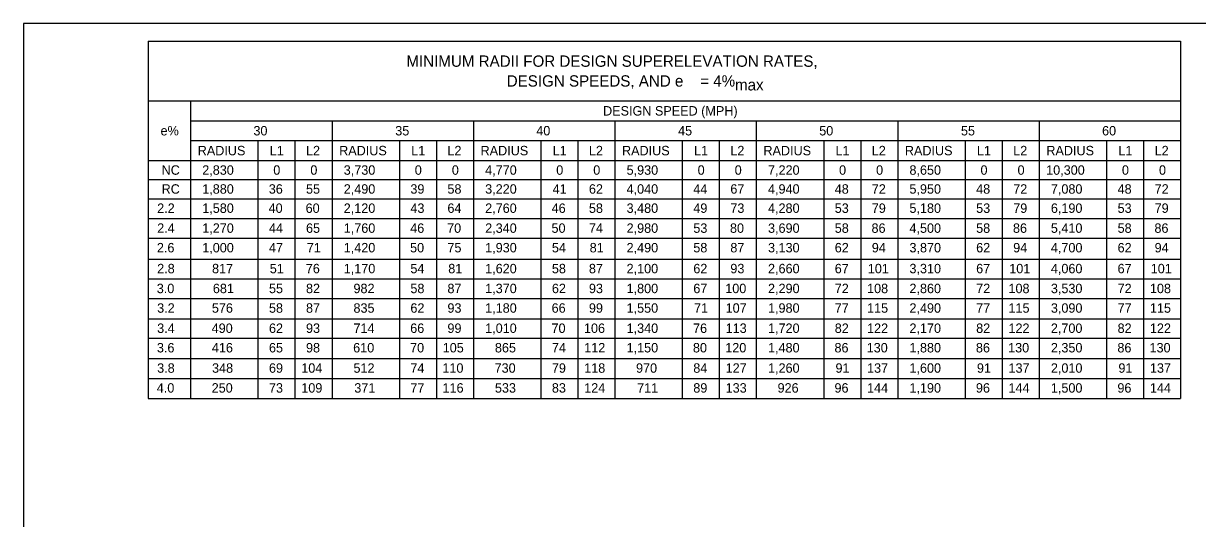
# Model space of a CAD drawing. Extents: x -404.8 to -373.6, y -458.1 to -437.7.
# Drawn here: x -404.83 to -386.16, y -445.54 to -437.68 of the extents above; entities that cross this region are included whole.
import ezdxf

# ---------------------------------------------------------------- set-up
doc = ezdxf.new("R2010")
doc.units = 0
for name, color, linetype in [('Bridge-Named Boundary', 7, 'Continuous'), ('Common-Notes', 7, 'Continuous'), ('Level 4', 7, 'Continuous')]:
    doc.layers.add(name, color=color, linetype=linetype)

msp = doc.modelspace()

# ---------------------------------------------------------------- linework, layer by layer
at = {"layer": 'Bridge-Named Boundary'}
msp.add_lwpolyline([(-404.826, -458.051), (-373.576, -458.051), (-373.576, -437.676), (-404.826, -437.676)], close=True, dxfattribs=at)
at = {"layer": 'Level 4'}
for p, q in [((-402.845, -437.957), (-386.425, -437.957)), ((-402.845, -437.957), (-402.845, -443.634)), ((-386.425, -437.957), (-386.425, -443.634)), ((-402.845, -438.906), (-386.425, -438.906)), ((-402.169, -438.906), (-402.169, -443.634)), ((-402.169, -439.222), (-386.425, -439.222)), ((-399.919, -439.222), (-399.919, -443.634)), ((-397.67, -439.222), (-397.67, -443.634)), ((-395.421, -439.222), (-395.421, -443.634)), ((-393.172, -439.222), (-393.172, -443.634)), ((-390.923, -439.222), (-390.923, -443.634)), ((-388.674, -439.222), (-388.674, -443.634)), ((-402.169, -439.538), (-386.425, -439.538)), ((-401.098, -439.538), (-401.098, -443.634)), ((-400.509, -439.538), (-400.509, -443.634)), ((-398.848, -439.538), (-398.848, -443.634)), ((-398.259, -439.538), (-398.259, -443.634)), ((-396.599, -439.538), (-396.599, -443.634)), ((-396.01, -439.538), (-396.01, -443.634)), ((-394.35, -439.538), (-394.35, -443.634)), ((-393.761, -439.538), (-393.761, -443.634)), ((-392.101, -439.538), (-392.101, -443.634)), ((-391.512, -439.538), (-391.512, -443.634)), ((-389.852, -439.538), (-389.852, -443.634)), ((-389.263, -439.538), (-389.263, -443.634)), ((-387.603, -439.538), (-387.603, -443.634)), ((-387.014, -439.538), (-387.014, -443.634)), ((-402.845, -439.855), (-386.425, -439.855)), ((-402.845, -440.155), (-386.425, -440.155)), ((-402.845, -440.461), (-386.425, -440.461)), ((-402.845, -440.777), (-386.425, -440.777)), ((-402.845, -441.088), (-386.425, -441.088)), ((-402.845, -441.42), (-386.425, -441.42)), ((-402.845, -441.736), (-386.425, -441.736)), ((-402.845, -442.047), (-386.425, -442.047)), ((-402.845, -442.369), (-386.425, -442.369)), ((-402.845, -442.679), (-386.425, -442.679)), ((-402.845, -443.001), (-386.425, -443.001)), ((-402.845, -443.317), (-386.425, -443.317)), ((-402.845, -443.634), (-386.425, -443.634))]:
    msp.add_line(p, q, dxfattribs=at)

# ---------------------------------------------------------------- texts
at = {"layer": 'Common-Notes'}
for s, height, p in [('MINIMUM RADII FOR DESIGN SUPERELEVATION RATES,', 0.18, (-398.737, -438.364)), ('DESIGN SPEEDS, AND e    = 4%', 0.18, (-397.141, -438.679)), ('DESIGN SPEED (MPH)', 0.15, (-395.609, -439.139)), ('e%', 0.15, (-402.646, -439.455)), ('30', 0.15, (-401.169, -439.455)), ('35', 0.15, (-398.914, -439.455)), ('40', 0.15, (-396.671, -439.455)), ('45', 0.15, (-394.416, -439.455)), ('50', 0.15, (-392.172, -439.455)), ('55', 0.15, (-389.918, -439.455)), ('60', 0.15, (-387.674, -439.455)), ('RADIUS', 0.15, (-402.055, -439.771)), ('L1', 0.15, (-400.909, -439.771)), ('L2', 0.15, (-400.333, -439.771)), ('RADIUS', 0.15, (-399.806, -439.771)), ('L1', 0.15, (-398.66, -439.771)), ('L2', 0.15, (-398.084, -439.771)), ('RADIUS', 0.15, (-397.557, -439.771)), ('L1', 0.15, (-396.411, -439.771)), ('L2', 0.15, (-395.834, -439.771)), ('RADIUS', 0.15, (-395.308, -439.771)), ('L1', 0.15, (-394.162, -439.771)), ('L2', 0.15, (-393.585, -439.771)), ('RADIUS', 0.15, (-393.059, -439.771)), ('L1', 0.15, (-391.913, -439.771)), ('L2', 0.15, (-391.336, -439.771)), ('RADIUS', 0.15, (-390.81, -439.771)), ('L1', 0.15, (-389.664, -439.771)), ('L2', 0.15, (-389.087, -439.771)), ('RADIUS', 0.15, (-388.56, -439.771)), ('L1', 0.15, (-387.414, -439.771)), ('L2', 0.15, (-386.838, -439.771)), ('NC', 0.15, (-402.629, -440.08)), ('2,830', 0.15, (-401.983, -440.08)), ('0', 0.15, (-400.853, -440.08)), ('0', 0.15, (-400.264, -440.08)), ('3,730', 0.15, (-399.733, -440.08)), ('0', 0.15, (-398.603, -440.08)), ('0', 0.15, (-398.014, -440.08)), ('4,770', 0.15, (-397.484, -440.08)), ('0', 0.15, (-396.354, -440.08)), ('0', 0.15, (-395.765, -440.08)), ('5,930', 0.15, (-395.235, -440.08)), ('0', 0.15, (-394.105, -440.08)), ('0', 0.15, (-393.516, -440.08)), ('7,220', 0.15, (-392.986, -440.08)), ('0', 0.15, (-391.856, -440.08)), ('0', 0.15, (-391.267, -440.08)), ('8,650', 0.15, (-390.737, -440.08)), ('0', 0.15, (-389.607, -440.08)), ('0', 0.15, (-389.018, -440.08)), ('10,300', 0.15, (-388.563, -440.08)), ('0', 0.15, (-387.358, -440.08)), ('0', 0.15, (-386.769, -440.08)), ('RC', 0.15, (-402.629, -440.381)), ('1,880', 0.15, (-401.983, -440.381)), ('36', 0.15, (-400.925, -440.381)), ('55', 0.15, (-400.333, -440.381)), ('2,490', 0.15, (-399.733, -440.381)), ('39', 0.15, (-398.673, -440.381)), ('58', 0.15, (-398.084, -440.381)), ('3,220', 0.15, (-397.484, -440.381)), ('41', 0.15, (-396.411, -440.381)), ('62', 0.15, (-395.834, -440.381)), ('4,040', 0.15, (-395.235, -440.381)), ('44', 0.15, (-394.174, -440.381)), ('67', 0.15, (-393.585, -440.381)), ('4,940', 0.15, (-392.986, -440.381)), ('48', 0.15, (-391.925, -440.381)), ('72', 0.15, (-391.336, -440.381)), ('5,950', 0.15, (-390.737, -440.381)), ('48', 0.15, (-389.676, -440.381)), ('72', 0.15, (-389.087, -440.381)), ('7,080', 0.15, (-388.488, -440.381)), ('48', 0.15, (-387.427, -440.381)), ('72', 0.15, (-386.838, -440.381)), ('2.2', 0.15, (-402.7, -440.686)), ('1,580', 0.15, (-401.983, -440.686)), ('40', 0.15, (-400.928, -440.686)), ('60', 0.15, (-400.339, -440.686)), ('2,120', 0.15, (-399.733, -440.686)), ('43', 0.15, (-398.673, -440.686)), ('64', 0.15, (-398.084, -440.686)), ('2,760', 0.15, (-397.484, -440.686)), ('46', 0.15, (-396.427, -440.686)), ('58', 0.15, (-395.834, -440.686)), ('3,480', 0.15, (-395.235, -440.686)), ('49', 0.15, (-394.174, -440.686)), ('73', 0.15, (-393.585, -440.686)), ('4,280', 0.15, (-392.986, -440.686)), ('53', 0.15, (-391.925, -440.686)), ('79', 0.15, (-391.336, -440.686)), ('5,180', 0.15, (-390.737, -440.686)), ('53', 0.15, (-389.676, -440.686)), ('79', 0.15, (-389.087, -440.686)), ('6,190', 0.15, (-388.488, -440.686)), ('53', 0.15, (-387.427, -440.686)), ('79', 0.15, (-386.838, -440.686)), ('2.4', 0.15, (-402.7, -441.003)), ('1,270', 0.15, (-401.983, -441.003)), ('44', 0.15, (-400.922, -441.003)), ('65', 0.15, (-400.333, -441.003)), ('1,760', 0.15, (-399.733, -441.003)), ('46', 0.15, (-398.676, -441.003)), ('70', 0.15, (-398.089, -441.003)), ('2,340', 0.15, (-397.484, -441.003)), ('50', 0.15, (-396.429, -441.003)), ('74', 0.15, (-395.834, -441.003)), ('2,980', 0.15, (-395.235, -441.003)), ('53', 0.15, (-394.174, -441.003)), ('80', 0.15, (-393.591, -441.003)), ('3,690', 0.15, (-392.986, -441.003)), ('58', 0.15, (-391.925, -441.003)), ('86', 0.15, (-391.34, -441.003)), ('4,500', 0.15, (-390.737, -441.003)), ('58', 0.15, (-389.676, -441.003)), ('86', 0.15, (-389.091, -441.003)), ('5,410', 0.15, (-388.488, -441.003)), ('58', 0.15, (-387.427, -441.003)), ('86', 0.15, (-386.841, -441.003)), ('2.6', 0.15, (-402.704, -441.314)), ('1,000', 0.15, (-401.983, -441.314)), ('47', 0.15, (-400.922, -441.314)), ('71', 0.15, (-400.32, -441.314)), ('1,420', 0.15, (-399.733, -441.314)), ('50', 0.15, (-398.678, -441.314)), ('75', 0.15, (-398.084, -441.314)), ('1,930', 0.15, (-397.484, -441.314)), ('54', 0.15, (-396.423, -441.314)), ('81', 0.15, (-395.822, -441.314)), ('2,490', 0.15, (-395.235, -441.314)), ('58', 0.15, (-394.174, -441.314)), ('87', 0.15, (-393.585, -441.314)), ('3,130', 0.15, (-392.986, -441.314)), ('62', 0.15, (-391.925, -441.314)), ('94', 0.15, (-391.336, -441.314)), ('3,870', 0.15, (-390.737, -441.314)), ('62', 0.15, (-389.676, -441.314)), ('94', 0.15, (-389.087, -441.314)), ('4,700', 0.15, (-388.488, -441.314)), ('62', 0.15, (-387.427, -441.314)), ('94', 0.15, (-386.838, -441.314)), ('2.8', 0.15, (-402.7, -441.646)), ('817', 0.15, (-401.827, -441.646)), ('51', 0.15, (-400.909, -441.646)), ('76', 0.15, (-400.336, -441.646)), ('1,170', 0.15, (-399.733, -441.646)), ('54', 0.15, (-398.673, -441.646)), ('81', 0.15, (-398.071, -441.646)), ('1,620', 0.15, (-397.484, -441.646)), ('58', 0.15, (-396.423, -441.646)), ('87', 0.15, (-395.834, -441.646)), ('2,100', 0.15, (-395.235, -441.646)), ('62', 0.15, (-394.174, -441.646)), ('93', 0.15, (-393.585, -441.646)), ('2,660', 0.15, (-392.986, -441.646)), ('67', 0.15, (-391.925, -441.646)), ('101', 0.15, (-391.399, -441.646)), ('3,310', 0.15, (-390.737, -441.646)), ('67', 0.15, (-389.676, -441.646)), ('101', 0.15, (-389.15, -441.646)), ('4,060', 0.15, (-388.488, -441.646)), ('67', 0.15, (-387.427, -441.646)), ('101', 0.15, (-386.9, -441.646)), ('3.0', 0.15, (-402.706, -441.962)), ('681', 0.15, (-401.814, -441.962)), ('55', 0.15, (-400.922, -441.962)), ('82', 0.15, (-400.333, -441.962)), ('982', 0.15, (-399.578, -441.962)), ('58', 0.15, (-398.673, -441.962)), ('87', 0.15, (-398.084, -441.962)), ('1,370', 0.15, (-397.484, -441.962)), ('62', 0.15, (-396.423, -441.962)), ('93', 0.15, (-395.834, -441.962)), ('1,800', 0.15, (-395.235, -441.962)), ('67', 0.15, (-394.174, -441.962)), ('100', 0.15, (-393.666, -441.962)), ('2,290', 0.15, (-392.986, -441.962)), ('72', 0.15, (-391.925, -441.962)), ('108', 0.15, (-391.411, -441.962)), ('2,860', 0.15, (-390.737, -441.962)), ('72', 0.15, (-389.676, -441.962)), ('108', 0.15, (-389.162, -441.962)), ('3,530', 0.15, (-388.488, -441.962)), ('72', 0.15, (-387.427, -441.962)), ('108', 0.15, (-386.913, -441.962)), ('3.2', 0.15, (-402.7, -442.273)), ('576', 0.15, (-401.83, -442.273)), ('58', 0.15, (-400.922, -442.273)), ('87', 0.15, (-400.333, -442.273)), ('835', 0.15, (-399.578, -442.273)), ('62', 0.15, (-398.673, -442.273)), ('93', 0.15, (-398.084, -442.273)), ('1,180', 0.15, (-397.484, -442.273)), ('66', 0.15, (-396.427, -442.273)), ('99', 0.15, (-395.834, -442.273)), ('1,550', 0.15, (-395.235, -442.273)), ('71', 0.15, (-394.162, -442.273)), ('107', 0.15, (-393.66, -442.273)), ('1,980', 0.15, (-392.986, -442.273)), ('77', 0.15, (-391.925, -442.273)), ('115', 0.15, (-391.411, -442.273)), ('2,490', 0.15, (-390.737, -442.273)), ('77', 0.15, (-389.676, -442.273)), ('115', 0.15, (-389.162, -442.273)), ('3,090', 0.15, (-388.488, -442.273)), ('77', 0.15, (-387.427, -442.273)), ('115', 0.15, (-386.913, -442.273)), ('3.4', 0.15, (-402.7, -442.594)), ('490', 0.15, (-401.833, -442.594)), ('62', 0.15, (-400.922, -442.594)), ('93', 0.15, (-400.333, -442.594)), ('714', 0.15, (-399.578, -442.594)), ('66', 0.15, (-398.676, -442.594)), ('99', 0.15, (-398.084, -442.594)), ('1,010', 0.15, (-397.484, -442.594)), ('70', 0.15, (-396.429, -442.594)), ('106', 0.15, (-395.913, -442.594)), ('1,340', 0.15, (-395.235, -442.594)), ('76', 0.15, (-394.178, -442.594)), ('113', 0.15, (-393.66, -442.594)), ('1,720', 0.15, (-392.986, -442.594)), ('82', 0.15, (-391.925, -442.594)), ('122', 0.15, (-391.411, -442.594)), ('2,170', 0.15, (-390.737, -442.594)), ('82', 0.15, (-389.676, -442.594)), ('122', 0.15, (-389.162, -442.594)), ('2,700', 0.15, (-388.488, -442.594)), ('82', 0.15, (-387.427, -442.594)), ('122', 0.15, (-386.913, -442.594)), ('3.6', 0.15, (-402.704, -442.904)), ('416', 0.15, (-401.83, -442.904)), ('65', 0.15, (-400.922, -442.904)), ('98', 0.15, (-400.333, -442.904)), ('610', 0.15, (-399.583, -442.904)), ('70', 0.15, (-398.678, -442.904)), ('105', 0.15, (-398.159, -442.904)), ('865', 0.15, (-397.329, -442.904)), ('74', 0.15, (-396.423, -442.904)), ('112', 0.15, (-395.909, -442.904)), ('1,150', 0.15, (-395.235, -442.904)), ('80', 0.15, (-394.18, -442.904)), ('120', 0.15, (-393.666, -442.904)), ('1,480', 0.15, (-392.986, -442.904)), ('86', 0.15, (-391.929, -442.904)), ('130', 0.15, (-391.417, -442.904)), ('1,880', 0.15, (-390.737, -442.904)), ('86', 0.15, (-389.68, -442.904)), ('130', 0.15, (-389.168, -442.904)), ('2,350', 0.15, (-388.488, -442.904)), ('86', 0.15, (-387.43, -442.904)), ('130', 0.15, (-386.919, -442.904)), ('3.8', 0.15, (-402.7, -443.227)), ('348', 0.15, (-401.827, -443.227)), ('69', 0.15, (-400.922, -443.227)), ('104', 0.15, (-400.408, -443.227)), ('512', 0.15, (-399.578, -443.227)), ('74', 0.15, (-398.673, -443.227)), ('110', 0.15, (-398.164, -443.227)), ('730', 0.15, (-397.334, -443.227)), ('79', 0.15, (-396.423, -443.227)), ('118', 0.15, (-395.909, -443.227)), ('970', 0.15, (-395.085, -443.227)), ('84', 0.15, (-394.174, -443.227)), ('127', 0.15, (-393.66, -443.227)), ('1,260', 0.15, (-392.986, -443.227)), ('91', 0.15, (-391.913, -443.227)), ('137', 0.15, (-391.411, -443.227)), ('1,600', 0.15, (-390.737, -443.227)), ('91', 0.15, (-389.664, -443.227)), ('137', 0.15, (-389.162, -443.227)), ('2,010', 0.15, (-388.488, -443.227)), ('91', 0.15, (-387.414, -443.227)), ('137', 0.15, (-386.913, -443.227)), ('4.0', 0.15, (-402.706, -443.543)), ('250', 0.15, (-401.833, -443.543)), ('73', 0.15, (-400.922, -443.543)), ('109', 0.15, (-400.408, -443.543)), ('371', 0.15, (-399.565, -443.543)), ('77', 0.15, (-398.673, -443.543)), ('116', 0.15, (-398.162, -443.543)), ('533', 0.15, (-397.329, -443.543)), ('83', 0.15, (-396.423, -443.543)), ('124', 0.15, (-395.909, -443.543)), ('711', 0.15, (-395.067, -443.543)), ('89', 0.15, (-394.174, -443.543)), ('133', 0.15, (-393.66, -443.543)), ('926', 0.15, (-392.834, -443.543)), ('96', 0.15, (-391.929, -443.543)), ('144', 0.15, (-391.411, -443.543)), ('1,190', 0.15, (-390.737, -443.543)), ('96', 0.15, (-389.68, -443.543)), ('144', 0.15, (-389.162, -443.543)), ('1,500', 0.15, (-388.488, -443.543)), ('96', 0.15, (-387.43, -443.543)), ('144', 0.15, (-386.913, -443.543))]:
    msp.add_text(s, height=height, dxfattribs=at).set_placement(p)
at = {"layer": 'Level 4'}
msp.add_text('max', height=0.18, dxfattribs=at).set_placement((-393.511, -438.74))

doc.saveas('drawing.dxf')
